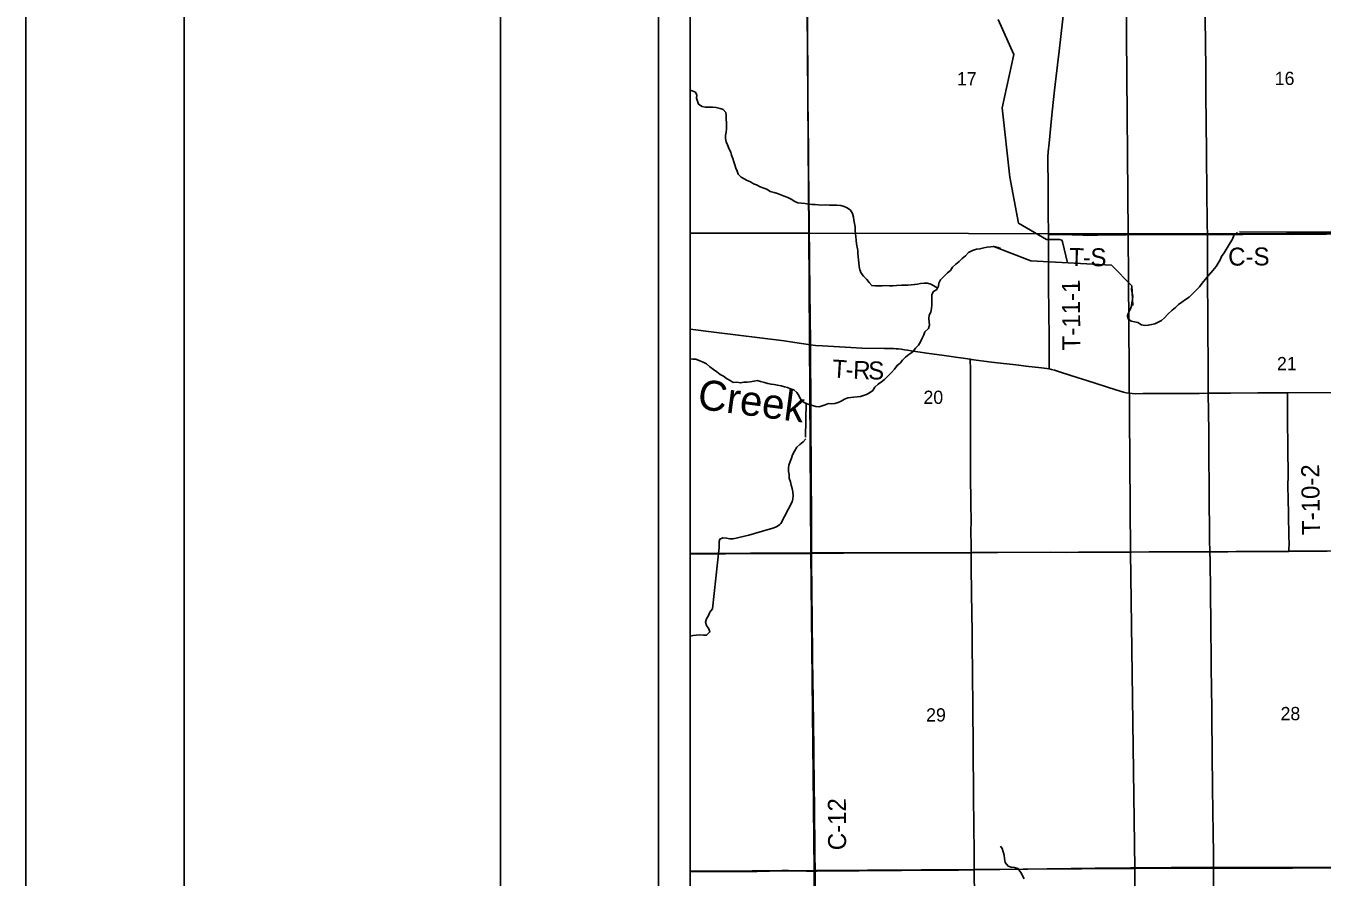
# Model space of a CAD drawing. Extents: x 0 to 34, y 0 to 22.
# Drawn here: x 0 to 4.098, y 16.618 to 19.309 of the extents above; entities that cross this region are included whole.
import ezdxf

# ---------------------------------------------------------------- set-up
doc = ezdxf.new("R2010")
doc.units = 0
for name, color, linetype in [('Default', 7, 'Continuous'), ('GM_X_County_Road', 7, 'Continuous'), ('GM_X_County_Road_Text', 7, 'Continuous'), ('GM_X_Minor_River', 7, 'Continuous'), ('GM_X_Minor_River_Text', 7, 'Continuous'), ('GM_X_Section', 7, 'Continuous'), ('GM_X_Section_Text', 7, 'Continuous'), ('GM_X_Township_Road', 7, 'Continuous'), ('GM_X_Township_Road_Text', 7, 'Continuous'), ('GM_X_US_Route', 7, 'Continuous'), ('SH_Border', 7, 'Continuous'), ('SH_Cut_Line', 7, 'Continuous'), ('SH_Data', 7, 'Continuous')]:
    doc.layers.add(name, color=color, linetype=linetype)

msp = doc.modelspace()

# ---------------------------------------------------------------- linework, layer by layer
at = {"layer": 'Default'}
for points in [[(2.1, 20.6957), (2.1, 16.6348), (2.2371, 16.6361), (2.3117, 16.6364), (2.3894, 16.638), (2.4111, 16.6382), (2.4673, 16.6374), (2.4945, 16.6372), (2.5004, 16.6372), (2.7674, 16.6388), (2.8856, 16.6396), (2.9477, 16.6404), (2.9977, 16.641), (3.0782, 16.6421), (3.1528, 16.643), (3.3798, 16.6456), (3.4917, 16.6469), (3.6204, 16.6476), (3.6236, 16.6475), (3.6462, 16.6479), (3.7301, 16.6476), (3.754, 16.6477), (3.8669, 16.648), (3.9365, 16.6479), (4.0639, 16.648), (4.2411, 16.648)], [(4.2411, 16.648), (4.0639, 16.648), (3.9365, 16.6479), (3.8669, 16.648), (3.754, 16.6477), (3.7301, 16.6476), (3.6462, 16.6479), (3.6236, 16.6475), (3.6204, 16.6476), (3.4917, 16.6469), (3.3798, 16.6456), (3.1528, 16.643), (3.0782, 16.6421), (2.9977, 16.641), (2.9477, 16.6404), (2.8856, 16.6396), (2.7674, 16.6388), (2.5004, 16.6372), (2.4945, 16.6372), (2.4673, 16.6374), (2.4111, 16.6382), (2.3894, 16.638), (2.3117, 16.6364), (2.2371, 16.6361), (2.1, 16.6348), (2.1, 14.1)]]:
    msp.add_lwpolyline(points, dxfattribs=at)
for points in [[(2.1, 19.6466), (2.1, 18.6532), (2.4755, 18.6539), (2.4678, 19.6478)], [(2.1, 18.6532), (2.1, 17.6408), (2.4811, 17.6426), (2.4755, 18.6539)], [(2.1, 17.6408), (2.1, 16.6364), (2.4922, 16.6384), (2.4811, 17.6426)], [(2.1, 16.6364), (2.1, 15.6339), (2.4995, 15.6374), (2.4922, 16.6384)]]:
    msp.add_lwpolyline(points, close=True, dxfattribs=at)
at = {"layer": 'GM_X_County_Road'}
for points in [[(2.4799, 18.3001), (2.4798, 18.3093), (2.4781, 18.4678), (2.4758, 18.6792), (2.4742, 18.8657), (2.4737, 18.9435), (2.4734, 18.9652), (2.4731, 18.9994), (2.4722, 19.0771), (2.4716, 19.1517), (2.4708, 19.2792), (2.4703, 19.3538), (2.4679, 19.6057), (2.4675, 19.6482)], [(3.735, 18.6489), (3.7343, 18.6815), (3.7335, 18.7902), (3.7331, 18.8181), (3.7327, 18.8647), (3.7322, 18.9113), (3.7306, 19.0916), (3.73, 19.1751), (3.7291, 19.2526), (3.7285, 19.3334), (3.728, 19.3863), (3.7277, 19.3981)], [(3.7378, 18.1472), (3.7374, 18.1905), (3.7361, 18.3957), (3.7355, 18.4983), (3.7352, 18.5511), (3.7349, 18.6195), (3.7352, 18.6412), (3.735, 18.6489)], [(3.735, 18.6489), (3.7913, 18.6492), (3.8472, 18.6494), (3.8939, 18.65), (4.0026, 18.6497), (4.1114, 18.6505), (4.1767, 18.651), (4.3384, 18.6517), (4.4843, 18.6526)], [(2.1, 18.3498), (2.1747, 18.3411), (2.3968, 18.313), (2.4307, 18.3084), (2.4799, 18.3001)], [(2.4832, 17.6413), (2.4834, 17.6784), (2.4832, 17.7095), (2.4831, 17.781), (2.4824, 17.865), (2.4824, 17.9053), (2.4819, 17.9581), (2.4818, 18.0015), (2.4818, 18.0512), (2.4812, 18.1165), (2.4812, 18.1632), (2.4806, 18.2253), (2.4805, 18.2657), (2.4799, 18.3001)], [(3.7432, 17.6465), (3.7421, 17.6842), (3.742, 17.6996), (3.7422, 17.7305), (3.7411, 17.7908), (3.7409, 17.8498), (3.7398, 17.9481), (3.7392, 18.0258), (3.7385, 18.0879), (3.7378, 18.1472)], [(2.4948, 16.6366), (2.4946, 16.6432), (2.4943, 16.6837), (2.4928, 16.8515), (2.4924, 16.892), (2.4904, 17.0225), (2.4894, 17.1033), (2.4883, 17.178), (2.4869, 17.3054), (2.4868, 17.324), (2.4865, 17.3458), (2.4864, 17.3645), (2.486, 17.3862), (2.4853, 17.4422), (2.4845, 17.5075), (2.4831, 17.6318), (2.4832, 17.6413)], [(3.7543, 16.6471), (3.7542, 16.6561), (3.7539, 16.6933), (3.7532, 16.7555), (3.7515, 16.8985), (3.7501, 17.0072), (3.7491, 17.122), (3.749, 17.1497), (3.7473, 17.2801), (3.7468, 17.3017), (3.7465, 17.3417), (3.746, 17.3726), (3.7457, 17.416), (3.7445, 17.5185), (3.7433, 17.6195), (3.7432, 17.6441), (3.7432, 17.6465)], [(2.1, 16.6342), (2.2374, 16.6355), (2.312, 16.6358), (2.3896, 16.6374), (2.4114, 16.6377), (2.4676, 16.6368), (2.4948, 16.6366)], [(2.4948, 16.6366), (2.5006, 16.6366), (2.7677, 16.6382), (2.8858, 16.6391), (2.9479, 16.6398), (2.9979, 16.6405)], [(2.5018, 15.6365), (2.5014, 15.6639), (2.501, 15.7044), (2.501, 15.7417), (2.5006, 15.8101), (2.4991, 15.9935), (2.4985, 16.1303), (2.4979, 16.1769), (2.4966, 16.3417), (2.4965, 16.4039), (2.4959, 16.4629), (2.4958, 16.5096), (2.4953, 16.5562), (2.495, 16.6277), (2.4948, 16.6366)], [(2.9979, 16.6405), (3.0785, 16.6415), (3.1531, 16.6424), (3.38, 16.645), (3.4919, 16.6463), (3.6206, 16.647), (3.6238, 16.6469), (3.6464, 16.6473), (3.7303, 16.6471), (3.7543, 16.6471)], [(3.7543, 16.6471), (3.8671, 16.6474), (3.9367, 16.6473), (4.0642, 16.6475), (4.2414, 16.6474), (4.3717, 16.6472), (4.409, 16.647), (4.5021, 16.6469)], [(3.7551, 16.4968), (3.7546, 16.5669), (3.7543, 16.6471)]]:
    msp.add_lwpolyline(points, dxfattribs=at)
at = {"layer": 'GM_X_Minor_River'}
for points in [[(3.2931, 18.5599), (3.2767, 18.6264), (3.2749, 18.631), (3.2677, 18.6337), (3.2571, 18.6338), (3.2268, 18.6334), (3.1382, 18.6847), (3.1106, 18.8303), (3.086, 19.0503), (3.1227, 19.2188), (3.0735, 19.329)], [(2.1375, 19.054), (2.1262, 19.0613), (2.1229, 19.0708), (2.1204, 19.0807), (2.1208, 19.0902), (2.1164, 19.0997), (2.1066, 19.104), (2.1, 19.1053)], [(2.8805, 18.4804), (2.8707, 18.4873), (2.8609, 18.4927), (2.8504, 18.4959), (2.8401, 18.496), (2.8284, 18.4942), (2.8189, 18.4928), (2.8094, 18.491), (2.7984, 18.4899), (2.7881, 18.4889), (2.7779, 18.489), (2.7677, 18.4887), (2.7521, 18.4881), (2.7411, 18.4871), (2.7305, 18.4872), (2.7184, 18.4877), (2.7066, 18.4874), (2.6952, 18.4868), (2.6854, 18.4869), (2.674, 18.4878), (2.6661, 18.4973), (2.6583, 18.5076), (2.6482, 18.518), (2.6403, 18.5276), (2.6366, 18.5375), (2.6341, 18.5485), (2.6331, 18.5595), (2.632, 18.5694), (2.6306, 18.5793), (2.63, 18.5888), (2.6297, 18.5983), (2.6279, 18.6089), (2.6261, 18.6199), (2.6244, 18.6313), (2.6233, 18.6416), (2.6227, 18.6511), (2.6217, 18.6632), (2.621, 18.6731), (2.6196, 18.6845), (2.6175, 18.6948), (2.6164, 18.7043), (2.6127, 18.7157), (2.6072, 18.726), (2.5966, 18.7333), (2.5865, 18.7383), (2.5762, 18.7407), (2.5637, 18.7416), (2.5524, 18.7421), (2.5406, 18.7426), (2.5274, 18.7427), (2.5164, 18.7421), (2.5046, 18.7433), (2.4948, 18.7442), (2.4845, 18.7447), (2.4739, 18.7455), (2.4637, 18.7471), (2.452, 18.748), (2.4402, 18.7497), (2.4304, 18.7535), (2.4195, 18.7616), (2.4089, 18.7659), (2.3972, 18.7706), (2.3863, 18.7745), (2.3765, 18.7787), (2.3651, 18.7823), (2.3531, 18.7858), (2.3425, 18.7927), (2.3323, 18.7955), (2.321, 18.8002), (2.31, 18.806), (2.3002, 18.8099), (2.2904, 18.816), (2.2806, 18.8203), (2.261, 18.8304), (2.2516, 18.8399), (2.2483, 18.8498), (2.2439, 18.8594), (2.2406, 18.8697), (2.2377, 18.8795), (2.2351, 18.8894), (2.2307, 18.9005), (2.2285, 18.91), (2.2233, 18.9195), (2.2181, 18.9333), (2.2133, 18.9428), (2.2115, 18.9534), (2.212, 18.9629), (2.214, 18.9731), (2.2149, 18.9834), (2.2146, 18.9932), (2.2143, 19.0027), (2.2141, 19.0141), (2.2138, 19.0251), (2.2124, 19.0346), (2.2045, 19.0442), (2.1943, 19.0477), (2.1818, 19.0509), (2.1705, 19.0517), (2.1599, 19.0515), (2.1477, 19.0524), (2.1375, 19.054)], [(3.4966, 18.4857), (3.4946, 18.4755), (3.4971, 18.4648), (3.4993, 18.4542), (3.498, 18.4436), (3.496, 18.4334), (3.4952, 18.4239), (3.4917, 18.414), (3.4866, 18.4039), (3.4827, 18.3936), (3.4834, 18.3838), (3.4939, 18.3757), (3.5049, 18.3733), (3.5155, 18.3713), (3.5271, 18.364), (3.5377, 18.3612), (3.5483, 18.3623), (3.5586, 18.3648), (3.5685, 18.3674), (3.5791, 18.3718), (3.5898, 18.3774), (3.5994, 18.3864), (3.6101, 18.3977), (3.6235, 18.4101), (3.6342, 18.4187), (3.6442, 18.4277), (3.6538, 18.4356), (3.6656, 18.4438), (3.6774, 18.4517), (3.6878, 18.4618), (3.6981, 18.472), (3.7104, 18.484), (3.7185, 18.4957), (3.7281, 18.5074), (3.7388, 18.5198), (3.7526, 18.5352), (3.763, 18.548), (3.7688, 18.5586), (3.775, 18.5691), (3.78, 18.5793), (3.7877, 18.5914), (3.7943, 18.6023), (3.8012, 18.6121), (3.807, 18.6235), (3.8144, 18.6348), (3.8183, 18.6461), (3.8282, 18.6551), (3.8305, 18.6555)], [(3.8362, 18.6577), (4.1334, 18.6567)], [(2.891, 18.5057), (2.9136, 18.5283), (2.9232, 18.5358), (2.9294, 18.5456), (2.9393, 18.5557), (2.95, 18.5636), (2.9596, 18.5734), (2.9699, 18.5824), (2.9803, 18.5925), (2.9929, 18.5988), (3.005, 18.6029), (3.016, 18.6039), (3.0282, 18.6068), (3.0385, 18.609), (3.0499, 18.6108), (3.0605, 18.6115), (3.0741, 18.6079), (3.0805, 18.6052)], [(3.0567, 18.6123), (3.1764, 18.5659), (3.4314, 18.5528), (3.4959, 18.4873), (3.499, 18.4254)], [(2.8283, 18.3105), (2.833, 18.3219), (2.8391, 18.3317), (2.8419, 18.3415), (2.853, 18.3524), (2.8569, 18.3626), (2.8555, 18.3725), (2.8549, 18.3839), (2.8553, 18.3941), (2.8611, 18.4043), (2.8631, 18.4149), (2.8636, 18.4255), (2.8634, 18.4369), (2.8635, 18.4502), (2.8644, 18.4597), (2.869, 18.4695), (2.8797, 18.4759), (2.8851, 18.4861), (2.8864, 18.4959), (2.891, 18.5057)], [(2.1, 18.2563), (2.1078, 18.2554), (2.1177, 18.2549), (2.1309, 18.2502), (2.1407, 18.246), (2.1516, 18.2402), (2.1625, 18.2309), (2.1738, 18.2221), (2.1847, 18.2152), (2.1949, 18.2071), (2.2051, 18.2013), (2.2152, 18.194), (2.2261, 18.1874), (2.2359, 18.1816), (2.2473, 18.1823), (2.259, 18.1803), (2.27, 18.1821), (2.2799, 18.182), (2.2894, 18.1834), (2.3019, 18.1859), (2.3114, 18.1874), (2.3224, 18.185), (2.3352, 18.181), (2.3451, 18.1783), (2.3556, 18.1759), (2.3655, 18.1747), (2.3757, 18.1727), (2.3878, 18.171), (2.3976, 18.1675), (2.4075, 18.1655), (2.4173, 18.1616), (2.4275, 18.1581), (2.4373, 18.1501), (2.4436, 18.1405), (2.4477, 18.131), (2.4548, 18.1214), (2.4649, 18.116), (2.4763, 18.1117), (2.4868, 18.1086), (2.4967, 18.1051), (2.5073, 18.105), (2.5168, 18.1079), (2.5267, 18.1112), (2.537, 18.1153), (2.5476, 18.1141), (2.5574, 18.1155), (2.5677, 18.1184), (2.5772, 18.1229), (2.5875, 18.1288), (2.5982, 18.1325), (2.6077, 18.134), (2.6171, 18.1346), (2.6274, 18.136), (2.6384, 18.1371), (2.6574, 18.143), (2.6673, 18.1485), (2.6769, 18.1564), (2.6838, 18.1662), (2.6942, 18.1764), (2.7045, 18.1839), (2.7144, 18.1913), (2.7251, 18.2015), (2.7363, 18.2128), (2.7455, 18.2237), (2.7539, 18.2354), (2.7635, 18.2425), (2.7716, 18.2523), (2.7811, 18.262), (2.7915, 18.2695), (2.8033, 18.2785), (2.8121, 18.2898), (2.8221, 18.3), (2.8283, 18.3105)], [(2.4665, 18.1171), (2.4649, 18.0082)], [(2.466, 18.0037), (2.4575, 17.9939), (2.4468, 17.9853), (2.4369, 17.9766), (2.4299, 17.9642), (2.423, 17.9529), (2.4198, 17.9419), (2.4159, 17.9313), (2.4116, 17.9196), (2.4111, 17.9101), (2.4103, 17.9002), (2.4124, 17.8903), (2.4131, 17.879), (2.4167, 17.8675), (2.4197, 17.8565), (2.4226, 17.8458), (2.424, 17.836), (2.425, 17.8238), (2.4245, 17.8136), (2.4225, 17.8037)], [(2.4225, 17.8037), (2.3861, 17.7358), (2.383, 17.732), (2.3727, 17.7253), (2.3579, 17.7194), (2.3468, 17.7164), (2.2856, 17.6984), (2.2362, 17.6872)], [(2.2362, 17.6872), (2.2248, 17.6873), (2.215, 17.6893), (2.2036, 17.6898), (2.1937, 17.6861), (2.1914, 17.6786), (2.192, 17.6656), (2.1914, 17.6602)], [(2.1914, 17.6602), (2.1704, 17.4654)], [(2.1704, 17.4654), (2.162, 17.4549), (2.1581, 17.4447), (2.1519, 17.4337), (2.1484, 17.4232), (2.1517, 17.4129), (2.1587, 17.4022), (2.1624, 17.3927), (2.1517, 17.3825), (2.1422, 17.3822), (2.1301, 17.3831), (2.1191, 17.3828), (2.1089, 17.3818), (2.1, 17.3798)], [(3.156, 16.6118), (3.1456, 16.6323), (3.1359, 16.6446), (3.1257, 16.6477), (3.1151, 16.649), (3.1053, 16.6525), (3.0955, 16.6643), (3.0938, 16.6769), (3.0924, 16.6871), (3.0895, 16.6974), (3.0858, 16.7077), (3.0813, 16.7153)]]:
    msp.add_lwpolyline(points, dxfattribs=at)
at = {"layer": 'GM_X_Section'}
for points in [[(2.4678, 19.6478), (3.4763, 19.6515), (3.4848, 18.6515), (2.4755, 18.6539)], [(3.4763, 19.6515), (4.4763, 19.663), (4.4846, 18.6535), (3.4848, 18.6515)], [(2.4755, 18.6539), (3.4848, 18.6515), (3.4923, 17.6455), (2.4811, 17.6426)], [(3.4848, 18.6515), (4.4846, 18.6535), (4.4933, 17.6509), (3.4923, 17.6455)], [(2.4811, 17.6426), (3.4923, 17.6455), (3.5053, 16.6448), (2.4922, 16.6384)], [(3.4923, 17.6455), (4.4933, 17.6509), (4.5021, 16.6472), (3.5053, 16.6448)], [(2.4922, 16.6384), (3.5053, 16.6448), (3.5041, 15.6366), (2.4995, 15.6374)], [(3.5053, 16.6448), (4.5021, 16.6472), (4.5104, 15.6416), (3.5041, 15.6366)]]:
    msp.add_lwpolyline(points, close=True, dxfattribs=at)
at = {"layer": 'GM_X_Township_Road'}
msp.add_line((3.2324, 18.6069), (3.2322, 18.6489), dxfattribs=at)
for points in [[(3.2322, 18.6489), (3.2319, 18.7206), (3.2316, 18.814), (3.2308, 18.8762), (3.2311, 18.8949), (3.2319, 18.9105), (3.2345, 18.9384), (3.2404, 18.9941), (3.2446, 19.0374), (3.2521, 19.1054), (3.2615, 19.1858), (3.2666, 19.229), (3.2784, 19.331), (3.2859, 19.3991)], [(3.2322, 18.6489), (3.2724, 18.649), (3.341, 18.6475), (3.3877, 18.6474), (3.4781, 18.6482), (3.6371, 18.6489), (3.7212, 18.6489), (3.735, 18.6489)], [(3.2348, 18.2249), (3.2348, 18.254), (3.2344, 18.3224), (3.2331, 18.4873), (3.2326, 18.5589), (3.2324, 18.6069)], [(2.4799, 18.3001), (2.4964, 18.2985), (2.5181, 18.297), (2.6081, 18.2917), (2.6423, 18.2904), (2.7138, 18.2892), (2.7324, 18.2888), (2.743, 18.2886), (2.7514, 18.288), (2.757, 18.2874), (2.7674, 18.2864), (2.7774, 18.2848), (2.787, 18.2835), (2.7989, 18.2814), (2.8127, 18.2797), (2.8557, 18.2732), (2.8951, 18.2677), (2.9181, 18.2643), (2.9456, 18.2603), (2.9628, 18.2579), (2.9854, 18.255)], [(2.9854, 18.255), (2.9887, 18.2546), (3.0528, 18.2462), (3.1393, 18.2362), (3.1609, 18.2334), (3.2103, 18.2274), (3.2279, 18.2257), (3.2348, 18.2249)], [(2.9884, 17.6434), (2.9878, 17.6725), (2.9876, 17.7036), (2.9877, 17.7503), (2.9874, 17.7907), (2.9865, 17.8995), (2.9863, 17.9742), (2.9861, 18.0428), (2.9858, 18.1451), (2.9856, 18.2217), (2.9854, 18.255)], [(3.2348, 18.2249), (3.2427, 18.2227), (3.2512, 18.2203), (3.2707, 18.2141), (3.327, 18.196), (3.3538, 18.1879), (3.4456, 18.1586), (3.4694, 18.1512), (3.4785, 18.1489), (3.4877, 18.1472), (3.497, 18.1463), (3.5064, 18.146), (3.5313, 18.1463), (3.5686, 18.1467), (3.7085, 18.147), (3.7378, 18.1472)], [(3.7378, 18.1472), (3.7738, 18.1475), (3.808, 18.1476), (3.8944, 18.1485), (3.9687, 18.1488), (3.988, 18.1488)], [(3.9926, 17.6471), (3.9929, 17.6535), (3.993, 17.6566), (3.9933, 17.6691), (3.9926, 17.6971), (3.9915, 17.7623), (3.9906, 17.8183), (3.9898, 17.8493), (3.9899, 17.8928), (3.9892, 17.9674), (3.9883, 18.0731), (3.9878, 18.1321), (3.988, 18.1488)], [(3.988, 18.1488), (4.1616, 18.1495), (4.2745, 18.1496), (4.3289, 18.1502), (4.3905, 18.1502), (4.4567, 18.1511), (4.4884, 18.1515)], [(2.9979, 16.6405), (2.9973, 16.6929), (2.9961, 16.8702), (2.9946, 17.032), (2.9935, 17.1533), (2.9924, 17.2621), (2.9913, 17.3523), (2.991, 17.3989), (2.9901, 17.4455), (2.9887, 17.5948), (2.9886, 17.6383), (2.9884, 17.6434)], [(2.1, 16.6342), (2.2374, 16.6355), (2.312, 16.6358), (2.3896, 16.6374), (2.4114, 16.6377), (2.4676, 16.6368), (2.4948, 16.6366)], [(2.4948, 16.6366), (2.5006, 16.6366), (2.7677, 16.6382), (2.8858, 16.6391), (2.9479, 16.6398), (2.9979, 16.6405)], [(2.9979, 16.6405), (3.0785, 16.6415), (3.1531, 16.6424), (3.38, 16.645), (3.4919, 16.6463), (3.6206, 16.647), (3.6238, 16.6469), (3.6464, 16.6473), (3.7303, 16.6471), (3.7543, 16.6471)], [(3.0086, 15.639), (3.0085, 15.646), (3.008, 15.702), (3.0076, 15.7331), (3.0076, 15.7611), (3.0069, 15.7984), (3.005, 15.9725), (3.0035, 16.1187), (3.0032, 16.1611), (3.0023, 16.2265), (3.0002, 16.4193), (2.9995, 16.4752), (2.9992, 16.5157), (2.9989, 16.553), (2.9979, 16.6405)], [(3.7543, 16.6471), (3.8671, 16.6474), (3.9367, 16.6473), (4.0642, 16.6475), (4.2414, 16.6474), (4.3717, 16.6472), (4.409, 16.647), (4.5021, 16.6469)]]:
    msp.add_lwpolyline(points, dxfattribs=at)
at = {"layer": 'GM_X_US_Route'}
msp.add_lwpolyline([(2.1, 17.6389), (2.2115, 17.6394), (2.4694, 17.6412), (2.4832, 17.6413), (2.5844, 17.6417), (2.9604, 17.6433), (2.9884, 17.6434), (3.0723, 17.6438), (3.2401, 17.6445), (3.2899, 17.6444), (3.3272, 17.6448), (3.3986, 17.6452), (3.495, 17.6455), (3.5509, 17.6458), (3.6845, 17.6462), (3.7432, 17.6465), (3.7529, 17.6465), (3.7995, 17.6465), (3.9394, 17.6466), (3.9926, 17.6471), (4.1134, 17.6482)], dxfattribs=at)
at = {"layer": 'SH_Border'}
for points in [[(0.5, 21.5), (1.5, 21.5), (1.5, 0.5), (0.5, 0.5)], [(1.5, 21.5), (33.5, 21.5), (33.5, 0.5), (1.5, 0.5)]]:
    msp.add_lwpolyline(points, close=True, dxfattribs=at)
at = {"layer": 'SH_Cut_Line'}
for points in [[(0, 0), (34, 0), (34, 22), (0, 22)], [(2.1, 20.6957), (2.1, 14.1), (8.9, 14.1), (8.9, 20.8277), (8.6079, 20.8216), (7.476, 20.811), (6.4789, 20.8005), (5.4741, 20.7803), (4.4698, 20.7584), (3.7151, 20.7343), (2.4566, 20.7022)]]:
    msp.add_lwpolyline(points, close=True, dxfattribs=at)
at = {"layer": 'SH_Data'}
for p, q in [((2, 21), (2, 14)), ((2.1, 20.9), (2.1, 14.1))]:
    msp.add_line(p, q, dxfattribs=at)

# ---------------------------------------------------------------- texts
at = {"layer": 'GM_X_County_Road_Text'}
for s, rotation, p in [('C-S', 0.4302, (3.8009, 18.5508)), ('C-12', 90.3442, (2.5929, 16.7027))]:
    msp.add_text(s, height=0.05682, rotation=rotation, dxfattribs=at).set_placement(p)
at = {"layer": 'GM_X_Minor_River_Text'}
msp.add_text('Creek', height=0.09476, rotation=352.5393, dxfattribs=at).set_placement((2.1203, 18.0987))
at = {"layer": 'GM_X_Section_Text'}
for s, p in [('17', (2.9434, 19.121)), ('16', (3.9479, 19.1221)), ('21', (3.955, 18.2203)), ('20', (2.8375, 18.1138)), ('29', (2.8459, 17.1096)), ('28', (3.9663, 17.1138))]:
    msp.add_text(s, height=0.04186, rotation=0, dxfattribs=at).set_placement(p)
at = {"layer": 'GM_X_Township_Road_Text'}
for s, height, rotation, p in [('T', 0.0568, 358.9242, (3.2981, 18.55)), ('S', 0.0568, 0.3199, (3.3655, 18.5488)), ('-', 0.0568, 359.1009, (3.3408, 18.5492)), ('T-11-1', 0.05682, 90.4943, (3.3336, 18.2831)), ('T', 0.0568, 356.2903, (2.5469, 18.1977)), ('R', 0.0568, 357.6189, (2.6141, 18.1935)), ('S', 0.0568, 359.0175, (2.6622, 18.1915)), ('-', 0.0568, 356.635, (2.5897, 18.1949)), ('T-10-2', 0.05682, 90.7388, (4.0911, 17.6995))]:
    msp.add_text(s, height=height, rotation=rotation, dxfattribs=at).set_placement(p)

doc.saveas('drawing.dxf')
